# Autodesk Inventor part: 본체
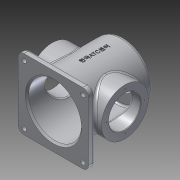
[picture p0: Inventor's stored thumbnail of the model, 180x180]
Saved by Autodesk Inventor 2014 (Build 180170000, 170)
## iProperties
Created: 2015-10
Part Number: 본체
Material: 알루미늄 6061
Document SubType Name: Modeling
Designer: Owner
Density: 2.71 g/cm^3
Appearance: 알루미늄 - 평지
Mass: 985.989 g
Surface Area: 1037.35 cm^2
Volume: 363.834 cm^3
Author: Owner
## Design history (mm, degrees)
sketch "스케치1"
  geometry: L1 (0, 80.726)-(0, -90.76); L2 (-27, 65)-(-40, 65); L3 (-40, 65)-(-40, 60); L4 (-40, 60)-(-50, 60); L5 (-50, 60)-(-50, -60); L6 (-50, -60)-(-45, -60); L7 (-45, -60)-(-45, 52); L8 (-45, 52)-(-27, 52); L9 (-27, 52)-(-27, 65); 1 further point
  constraints: 18 end point, 6 parallel, 2 perpendicular, 1 point on line, 1 vertical
  dimensions: "d0" = 90 diameter of L7 L1; "d1" = 54 diameter of L9 L1; "d2" = 80 diameter of L3 L1; "d3" = 100 diameter of L5 L1; "d4" = 120 distance between parallel lines of L6 L4; "d5" = 13 distance between parallel lines of L2 L8; "d6" = 5 distance between parallel lines of L2 L4; "d7" = 60 distance from line of L6 point (0, 0)
revolve "회전1" sketch "스케치1" stored, may be unused: angle "d8" = 90 deg
node "작업 평면1"
sketch "스케치2"
  geometry: L1 (50, -60)-(-50, -60); L2 (-60, -50)-(-60, 50); L3 (-50, 60)-(50, 60); L4 (60, 50)-(60, -50); L5 (60, -60)-(-60, 60); L6 (-60, -60)-(60, 60); C1 r 45 at (0, 0) reference; A1 r 10 centre (-50, 50) between (-50, 60) and (-60, 50); A2 r 10 centre (50, 50) between (60, 50) and (50, 60); A3 r 10 centre (50, -50) between (50, -60) and (60, -50); A4 r 10 centre (-50, -50) between (-60, -50) and (-50, -60); 1 further point
  constraints: 12 end point, 8 point on circle, 8 point on line, 8 tangent, 4 centre point, 3 equal radius, 2 midpoint, 2 parallel, 1 horizontal, 1 perpendicular
  dimensions: "d10" = 120 distance of L5.end L6.end; "d11" = 120 distance of L6.start L5.end; "d12" = 10 radius of A1
extrude "돌출1" join sketch "스케치2" distance "d13" = 10; taper "d14" = 0 deg
node "작업 평면3"
  node "작업 평면2"
sketch "스케치4"
  geometry: C1 r 40 at (0, 0); 1 further point
  constraints: 1 centre point, 1 coincident
  dimensions: "d17" = 80 diameter of C1
extrude "돌출2" join sketch "스케치4" stored distance "d18" = 10; taper "d19" = 0 deg
hole "구멍1" diameter "d22" = 54; stored, may be unused: countersink angle "d26" = 90 deg, drill point angle "d28" = 0 deg; dims "d20" = 10, "d21" = 10, "d23" = 6, "d24" = 4, "d25" = 2, "d27" = 8
sketch "스케치5" dims "d29" = 65
  geometry: L1 (0, 0)-(40.527, 40.527); L2 (0, 0)-(57.313, 0); C1 r 27 at (0, 0) reference; 2 further points
  constraints: 4 end point, 2 coincident, 1 equal length, 1 horizontal, 1 point on line, 3 other
  dimensions: "d30" = 45 deg angle of L2 L1
hole "구멍2" sketch "스케치5" at (22.981, 22.981) diameter "d31" = 3.242; stored, may be unused: countersink angle "d35" = 90 deg, drill point angle "d37" = 118 deg; dims "d32" = 8, "d33" = 4, "d34" = 2, "d36" = 10
sketch "스케치6"
  geometry: C1 r 27 at (0, 0) reference; 1 further point
  constraints: 1 vertical alignment
  dimensions: "d42" = 32.5 distance of C1.centre point (0, 32.5)
hole "구멍3" sketch "스케치6" at (0, 32.5) diameter "d43" = 3.242; stored, may be unused: countersink angle "d47" = 90 deg, drill point angle "d49" = 118 deg; dims "d44" = 8, "d45" = 4, "d46" = 2, "d48" = 10
sketch "스케치7"
  geometry: A1 r 10 centre (-50, -50) between (-60, -50) and (-50, -60) reference; A2 r 10 centre (50, -50) between (50, -60) and (60, -50) reference; A3 r 10 centre (50, 50) between (60, 50) and (50, 60) reference; A4 r 10 centre (-50, 50) between (-50, 60) and (-60, 50) reference; 4 further points
  constraints: 4 coincident
hole "구멍4" sketch "스케치7" at (-50, 50), (-50, -50), (50, -50), (50, 50) diameter "d53" = 8; stored, may be unused: countersink angle "d57" = 90 deg, drill point angle "d59" = 0 deg; dims "d54" = 8, "d55" = 4, "d56" = 2, "d58" = 10
fillet "모깎기1" dims "d60" = 5, "d61" = 3
chamfer "모따기1" distance "d62" = 3; stored, may be unused: second distance "d63" = 2, angle "d64" = 45 deg
chamfer "모따기2" distance "d65" = 1; stored, may be unused: second distance "d66" = 2, angle "d67" = 45 deg
node "작업 평면7"
sketch "스케치8"
  geometry: L1 (50, -60)-(-50, -60) reference; 2 further points
  constraints: 1 vertical alignment, 1 other
  dimensions: "d68" = 70 distance from line of L1 point (0, 10)
feature "엠보싱1" sketch "스케치8" dims "d0" = 90, "d1" = 54, "d2" = 80, "d3" = 100, "d4" = 120, "d5" = 13, "d6" = 5, "d7" = 60, "d69" = 0.5, "d70" = 0
node "솔리드1"
pattern_circular "원형 패턴2" dims angle "d51" = 360 deg
pattern_circular "원형 패턴1" dims angle "d39" = 360 deg
mirror "대칭1"
other parameters: "d15" = 12
